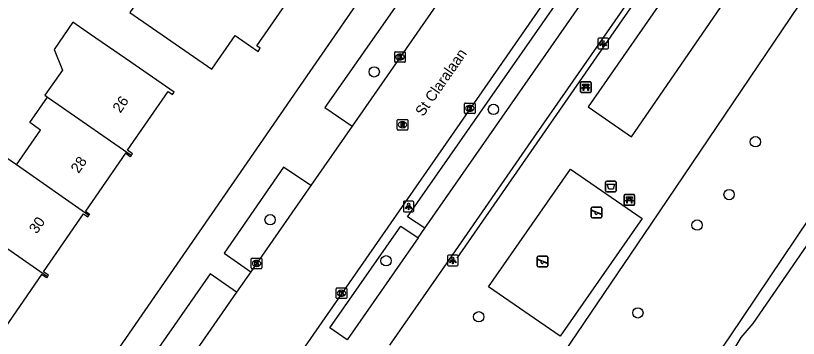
# Model space of a CAD drawing. Extents: x 160158 to 160921, y 381517 to 382041.
# Drawn here: x 160666.6 to 160740.7, y 381660.1 to 381690.7 of the extents above; entities that cross this region are included whole.
import ezdxf

# ---------------------------------------------------------------- set-up
doc = ezdxf.new("R2010")
doc.units = 0
for name, color, linetype in [('IMGEO_Afvalbak', 7, 'Continuous'), ('IMGEO_Bank', 7, 'Continuous'), ('IMGEO_Boom', 7, 'Continuous'), ('IMGEO_Fietspad_open', 7, 'Continuous'), ('IMGEO_Groenvoorziening', 7, 'Continuous'), ('IMGEO_Hek', 7, 'Continuous'), ('IMGEO_Kolk', 7, 'Continuous'), ('IMGEO_Lichtpunt', 7, 'Continuous'), ('IMGEO_Loofbos', 7, 'Continuous'), ('IMGEO_Openbare_ruimte_label', 7, 'Continuous'), ('IMGEO_Pand', 7, 'Continuous'), ('IMGEO_Pand_nummerreeks', 7, 'Continuous'), ('IMGEO_Rijbaan_lokaal_open', 7, 'Continuous'), ('IMGEO_Rioolput', 7, 'Continuous'), ('IMGEO_Speelvoorziening', 7, 'Continuous'), ('IMGEO_Voetpad_open', 7, 'Continuous'), ('IMGEO_Waterloop', 7, 'Continuous')]:
    doc.layers.add(name, color=color, linetype=linetype)

msp = doc.modelspace()

# ---------------------------------------------------------------- linework, layer by layer
at = {"layer": 'IMGEO_Afvalbak'}
for p, q in [((160722.423, 381674.074), (160722.423, 381674.874)), ((160722.423, 381674.874), (160722.423, 381674.074)), ((160722.523, 381674.974), (160723.313, 381674.974)), ((160723.313, 381674.974), (160722.523, 381674.974)), ((160723.413, 381674.874), (160723.413, 381674.074)), ((160723.413, 381674.074), (160723.413, 381674.874)), ((160723.313, 381673.974), (160722.523, 381673.974)), ((160722.523, 381673.974), (160723.313, 381673.974))]:
    msp.add_line(p, q, dxfattribs=at)
msp.add_lwpolyline([(160722.566, 381674.688), (160723.27, 381674.688), (160723.121, 381674.218), (160722.715, 381674.218), (160722.566, 381674.688)], dxfattribs=at)
for centre, start, end in [((160722.523, 381674.874), 90, 180), ((160722.523, 381674.874), 90, 180), ((160723.313, 381674.874), 0, 90), ((160723.313, 381674.874), 360, 90), ((160722.523, 381674.074), 180, 270), ((160722.523, 381674.074), 180, 270), ((160723.313, 381674.074), 270, 0), ((160723.313, 381674.074), 270, 0)]:
    msp.add_arc(centre, 0.1, start, end, dxfattribs=at)
at = {"layer": 'IMGEO_Bank'}
for p, q in [((160720.047, 381683.461), (160720.047, 381684.302)), ((160720.047, 381684.302), (160720.047, 381683.461)), ((160720.122, 381684.386), (160720.963, 381684.386)), ((160720.963, 381684.386), (160720.122, 381684.386)), ((160720.744, 381683.784), (160720.351, 381683.784)), ((160720.356, 381683.892), (160720.356, 381683.998)), ((160720.4, 381683.998), (160720.4, 381683.892)), ((160720.688, 381684.004), (160720.406, 381684.004)), ((160720.406, 381683.886), (160720.688, 381683.886)), ((160720.694, 381683.892), (160720.694, 381683.998)), ((160720.738, 381683.998), (160720.738, 381683.892)), ((160721.047, 381684.311), (160721.047, 381683.47)), ((160721.047, 381683.47), (160721.047, 381684.311)), ((160720.972, 381683.386), (160720.131, 381683.386)), ((160720.131, 381683.386), (160720.972, 381683.386)), ((160724.166, 381672.785), (160724.166, 381673.626)), ((160724.166, 381673.626), (160724.166, 381672.785)), ((160724.241, 381673.71), (160725.082, 381673.71)), ((160725.082, 381673.71), (160724.241, 381673.71)), ((160725.166, 381673.635), (160725.166, 381672.794)), ((160725.166, 381672.794), (160725.166, 381673.635)), ((160725.091, 381672.71), (160724.25, 381672.71)), ((160724.25, 381672.71), (160725.091, 381672.71)), ((160724.863, 381673.108), (160724.47, 381673.108)), ((160724.475, 381673.216), (160724.475, 381673.322)), ((160724.519, 381673.322), (160724.519, 381673.216)), ((160724.807, 381673.328), (160724.525, 381673.328)), ((160724.525, 381673.21), (160724.807, 381673.21)), ((160724.813, 381673.216), (160724.813, 381673.322)), ((160724.857, 381673.322), (160724.857, 381673.216))]:
    msp.add_line(p, q, dxfattribs=at)
for points in [[(160720.294, 381683.784), (160720.152, 381683.784), (160720.264, 381683.886), (160720.35, 381683.886)], [(160720.35, 381684.004), (160720.264, 381684.004), (160720.264, 381684.165), (160720.827, 381684.165), (160720.827, 381684.004), (160720.744, 381684.004)], [(160720.344, 381683.777), (160720.344, 381683.57), (160720.301, 381683.57), (160720.301, 381683.777)], [(160720.744, 381683.886), (160720.827, 381683.886), (160720.939, 381683.784), (160720.8, 381683.784)], [(160720.794, 381683.777), (160720.794, 381683.57), (160720.75, 381683.57), (160720.75, 381683.777)], [(160724.469, 381673.328), (160724.383, 381673.328), (160724.383, 381673.489), (160724.946, 381673.489), (160724.946, 381673.328), (160724.863, 381673.328)], [(160724.413, 381673.108), (160724.271, 381673.108), (160724.383, 381673.21), (160724.469, 381673.21)], [(160724.463, 381673.101), (160724.463, 381672.894), (160724.42, 381672.894), (160724.42, 381673.101)], [(160724.863, 381673.21), (160724.946, 381673.21), (160725.058, 381673.108), (160724.919, 381673.108)], [(160724.913, 381673.101), (160724.913, 381672.894), (160724.869, 381672.894), (160724.869, 381673.101)]]:
    msp.add_lwpolyline(points, dxfattribs=at)
for centre, radius, start, end in [((160720.125, 381684.308), 0.0779, 92.4484, 184.28452), ((160720.125, 381684.308), 0.0779, 92.4484, 184.28452), ((160720.294, 381683.777), 0.00671, 2.89567, 87.10433), ((160720.351, 381683.777), 0.00671, 92.89567, 177.10433), ((160720.349, 381683.997), 0.00671, 2.89567, 87.10433), ((160720.349, 381683.893), 0.00671, 272.89567, 357.10433), ((160720.406, 381683.997), 0.00671, 92.89567, 177.10433), ((160720.406, 381683.893), 0.00671, 182.89567, 267.10433), ((160720.688, 381683.997), 0.00671, 2.89567, 87.10433), ((160720.688, 381683.893), 0.00671, 272.89567, 357.10433), ((160720.745, 381683.997), 0.00671, 92.89567, 177.10433), ((160720.745, 381683.893), 0.00671, 182.89567, 267.10433), ((160720.743, 381683.777), 0.00671, 2.89567, 87.10433), ((160720.8, 381683.777), 0.00671, 92.89567, 177.10433), ((160720.969, 381684.308), 0.0779, 2.4484, 94.28452), ((160720.969, 381684.308), 0.0779, 2.4484, 94.28452), ((160720.125, 381683.464), 0.0779, 182.4484, 274.28452), ((160720.125, 381683.464), 0.0779, 182.4484, 274.28452), ((160720.969, 381683.464), 0.0779, 272.4484, 4.28452), ((160720.969, 381683.464), 0.0779, 272.4484, 4.28452), ((160724.244, 381673.632), 0.0779, 92.4484, 184.28452), ((160724.244, 381673.632), 0.0779, 92.4484, 184.28452), ((160725.088, 381673.632), 0.0779, 2.4484, 94.28452), ((160725.088, 381673.632), 0.0779, 2.4484, 94.28452), ((160724.244, 381672.788), 0.0779, 182.4484, 274.28452), ((160724.244, 381672.788), 0.0779, 182.4484, 274.28452), ((160724.413, 381673.101), 0.00671, 2.89567, 87.10433), ((160724.47, 381673.101), 0.00671, 92.89567, 177.10433), ((160724.468, 381673.321), 0.00671, 2.89567, 87.10433), ((160724.468, 381673.217), 0.00671, 272.89567, 357.10433), ((160724.525, 381673.321), 0.00671, 92.89567, 177.10433), ((160724.525, 381673.217), 0.00671, 182.89567, 267.10433), ((160724.807, 381673.321), 0.00671, 2.89567, 87.10433), ((160724.807, 381673.217), 0.00671, 272.89567, 357.10433), ((160724.864, 381673.321), 0.00671, 92.89567, 177.10433), ((160724.864, 381673.217), 0.00671, 182.89567, 267.10433), ((160724.862, 381673.101), 0.00671, 2.89567, 87.10433), ((160724.919, 381673.101), 0.00671, 92.89567, 177.10433), ((160725.088, 381672.788), 0.0779, 272.4484, 4.28452), ((160725.088, 381672.788), 0.0779, 272.4484, 4.28452)]:
    msp.add_arc(centre, radius, start, end, dxfattribs=at)
at = {"layer": 'IMGEO_Boom'}
for centre in [(160700.516, 381685.34), (160711.805, 381681.78), (160736.598, 381678.723), (160734.111, 381673.707), (160690.669, 381671.331), (160731.077, 381670.823), (160701.64, 381667.44), (160710.41, 381662.131), (160725.469, 381662.504)]:
    msp.add_circle(centre, 0.489, dxfattribs=at)
at = {"layer": 'IMGEO_Fietspad_open'}
for points in [[(160750.884, 381729.902), (160715.353, 381678.728), (160707.599, 381667.561), (160701.965, 381659.446)], [(160705.315, 381670.539), (160726.771, 381701.377)], [(160704.668, 381669.608), (160705.315, 381670.539)], [(160704.668, 381669.608), (160697.946, 381659.948)]]:
    msp.add_lwpolyline(points, dxfattribs=at)
at = {"layer": 'IMGEO_Groenvoorziening'}
for points in [[(160720.77, 381682.025), (160724.882, 381679.185), (160733.282, 381691.433), (160729.203, 381694.182), (160720.77, 381682.025)], [(160725.872, 381671.46), (160718.106, 381660.295), (160711.346, 381664.96), (160719.106, 381676.122), (160725.872, 381671.46)]]:
    msp.add_lwpolyline(points, dxfattribs=at)
at = {"layer": 'IMGEO_Hek'}
msp.add_lwpolyline([(160735.576, 381706.994), (160708.335, 381667.698)], dxfattribs=at)
at = {"layer": 'IMGEO_Kolk'}
for p, q in [((160702.46, 381686.319), (160702.46, 381687.171)), ((160702.535, 381687.245), (160703.387, 381687.245)), ((160702.948, 381687.025), (160702.973, 381687.025)), ((160703.461, 381687.171), (160703.461, 381686.319)), ((160703.387, 381686.245), (160702.535, 381686.245)), ((160702.971, 381686.465), (160702.946, 381686.465)), ((160709.072, 381681.461), (160709.072, 381682.313)), ((160709.147, 381682.387), (160709.999, 381682.387)), ((160710.073, 381682.313), (160710.073, 381681.461)), ((160709.583, 381681.607), (160709.558, 381681.607)), ((160709.56, 381682.167), (160709.585, 381682.167)), ((160709.999, 381681.387), (160709.147, 381681.387)), ((160688.883, 381666.759), (160688.883, 381667.611)), ((160688.958, 381667.685), (160689.81, 381667.685)), ((160689.371, 381667.465), (160689.396, 381667.465)), ((160689.884, 381667.611), (160689.884, 381666.759)), ((160689.394, 381666.905), (160689.369, 381666.905)), ((160689.81, 381666.685), (160688.958, 381666.685)), ((160696.918, 381663.94), (160696.918, 381664.792)), ((160696.993, 381664.866), (160697.845, 381664.866)), ((160697.406, 381664.646), (160697.431, 381664.646)), ((160697.919, 381664.792), (160697.919, 381663.94)), ((160697.845, 381663.866), (160696.993, 381663.866)), ((160697.429, 381664.086), (160697.404, 381664.086))]:
    msp.add_line(p, q, dxfattribs=at)
for points in [[(160702.46, 381686.319), (160702.46, 381687.171)], [(160702.535, 381687.245), (160703.387, 381687.245)], [(160702.781, 381686.945), (160702.904, 381686.945), (160702.904, 381686.794), (160703.034, 381686.945), (160703.198, 381686.945), (160703.052, 381686.794), (160703.205, 381686.545), (160703.053, 381686.545), (160702.968, 381686.709), (160702.904, 381686.642), (160702.904, 381686.545), (160702.781, 381686.545), (160702.781, 381686.945)], [(160703.461, 381687.171), (160703.461, 381686.319)], [(160703.387, 381686.245), (160702.535, 381686.245)], [(160709.072, 381681.461), (160709.072, 381682.313)], [(160709.147, 381682.387), (160709.999, 381682.387)], [(160710.073, 381682.313), (160710.073, 381681.461)], [(160709.393, 381682.087), (160709.516, 381682.087), (160709.516, 381681.936), (160709.646, 381682.087), (160709.81, 381682.087), (160709.664, 381681.936), (160709.817, 381681.687), (160709.665, 381681.687), (160709.58, 381681.851), (160709.516, 381681.784), (160709.516, 381681.687), (160709.393, 381681.687), (160709.393, 381682.087)], [(160709.999, 381681.387), (160709.147, 381681.387)], [(160688.883, 381666.759), (160688.883, 381667.611)], [(160688.958, 381667.685), (160689.81, 381667.685)], [(160689.884, 381667.611), (160689.884, 381666.759)], [(160689.204, 381667.385), (160689.327, 381667.385), (160689.327, 381667.234), (160689.457, 381667.385), (160689.621, 381667.385), (160689.475, 381667.234), (160689.628, 381666.985), (160689.476, 381666.985), (160689.391, 381667.149), (160689.327, 381667.082), (160689.327, 381666.985), (160689.204, 381666.985), (160689.204, 381667.385)], [(160689.81, 381666.685), (160688.958, 381666.685)], [(160696.918, 381663.94), (160696.918, 381664.792)], [(160696.993, 381664.866), (160697.845, 381664.866)], [(160697.239, 381664.566), (160697.362, 381664.566), (160697.362, 381664.415), (160697.492, 381664.566), (160697.656, 381664.566), (160697.51, 381664.415), (160697.663, 381664.166), (160697.511, 381664.166), (160697.426, 381664.33), (160697.362, 381664.263), (160697.362, 381664.166), (160697.239, 381664.166), (160697.239, 381664.566)], [(160697.919, 381664.792), (160697.919, 381663.94)], [(160697.845, 381663.866), (160696.993, 381663.866)]]:
    msp.add_lwpolyline(points, dxfattribs=at)
for centre, start, end in [((160702.537, 381687.169), 91.55205, 178.44795), ((160702.537, 381687.169), 91.55205, 178.44795), ((160703.385, 381687.169), 1.55205, 88.44795), ((160703.385, 381687.169), 1.55205, 88.44795), ((160702.537, 381686.321), 181.55205, 268.44795), ((160702.537, 381686.321), 181.55205, 268.44795), ((160703.385, 381686.321), 271.55205, 358.44795), ((160703.385, 381686.321), 271.55205, 358.44795), ((160709.149, 381682.311), 91.55205, 178.44795), ((160709.149, 381682.311), 91.55205, 178.44795), ((160709.997, 381682.311), 1.55205, 88.44795), ((160709.997, 381682.311), 1.55205, 88.44795), ((160709.149, 381681.463), 181.55205, 268.44795), ((160709.149, 381681.463), 181.55205, 268.44795), ((160709.997, 381681.463), 271.55205, 358.44795), ((160709.997, 381681.463), 271.55205, 358.44795), ((160688.96, 381667.609), 91.55205, 178.44795), ((160688.96, 381667.609), 91.55205, 178.44795), ((160689.808, 381667.609), 1.55205, 88.44795), ((160689.808, 381667.609), 1.55205, 88.44795), ((160688.96, 381666.761), 181.55205, 268.44795), ((160688.96, 381666.761), 181.55205, 268.44795), ((160689.808, 381666.761), 271.55205, 358.44795), ((160689.808, 381666.761), 271.55205, 358.44795), ((160696.995, 381664.79), 91.55205, 178.44795), ((160696.995, 381664.79), 91.55205, 178.44795), ((160697.843, 381664.79), 1.55205, 88.44795), ((160697.843, 381664.79), 1.55205, 88.44795), ((160696.995, 381663.942), 181.55205, 268.44795), ((160696.995, 381663.942), 181.55205, 268.44795), ((160697.843, 381663.942), 271.55205, 358.44795), ((160697.843, 381663.942), 271.55205, 358.44795)]:
    msp.add_arc(centre, 0.0765, start, end, dxfattribs=at)
for centre, major_axis, ratio, start_param, end_param in [((160702.947, 381686.745), (-0.387, 0.002), 0.722429, 4.712389, 7.853982), ((160702.972, 381686.745), (-0.39, 0.002), 0.717154, 1.570796, 4.712389), ((160709.559, 381681.887), (-0.387, 0.002), 0.722429, 4.712389, 7.853982), ((160709.584, 381681.887), (-0.39, 0.002), 0.717154, 1.570796, 4.712389), ((160689.37, 381667.185), (-0.387, 0.002), 0.722429, 4.712389, 7.853982), ((160689.395, 381667.185), (-0.39, 0.002), 0.717154, 1.570796, 4.712389), ((160697.405, 381664.366), (-0.387, 0.002), 0.722429, 4.712389, 7.853982), ((160697.43, 381664.366), (-0.39, 0.002), 0.717154, 1.570796, 4.712389)]:
    msp.add_ellipse(centre, major_axis=major_axis, ratio=ratio, start_param=start_param, end_param=end_param, dxfattribs=at)
at = {"layer": 'IMGEO_Lichtpunt'}
for p, q in [((160721.689, 381688.424), (160721.689, 381687.617)), ((160721.689, 381688.424), (160721.689, 381687.617)), ((160722.591, 381688.519), (160721.783, 381688.519)), ((160722.591, 381688.519), (160721.783, 381688.519)), ((160722.685, 381687.617), (160722.685, 381688.424)), ((160722.685, 381687.617), (160722.685, 381688.424)), ((160721.783, 381687.523), (160722.591, 381687.523)), ((160721.783, 381687.523), (160722.591, 381687.523)), ((160703.277, 381672.986), (160703.277, 381672.179)), ((160703.277, 381672.986), (160703.277, 381672.179)), ((160704.179, 381673.081), (160703.371, 381673.081)), ((160704.179, 381673.081), (160703.371, 381673.081)), ((160704.273, 381672.179), (160704.273, 381672.986)), ((160704.273, 381672.179), (160704.273, 381672.986)), ((160703.371, 381672.085), (160704.179, 381672.085)), ((160703.371, 381672.085), (160704.179, 381672.085)), ((160707.459, 381667.87), (160707.459, 381667.063)), ((160707.459, 381667.87), (160707.459, 381667.063)), ((160708.361, 381667.965), (160707.553, 381667.965)), ((160708.361, 381667.965), (160707.553, 381667.965)), ((160708.455, 381667.063), (160708.455, 381667.87)), ((160708.455, 381667.063), (160708.455, 381667.87)), ((160707.553, 381666.969), (160708.361, 381666.969)), ((160707.553, 381666.969), (160708.361, 381666.969))]:
    msp.add_line(p, q, dxfattribs=at)
for points in [[(160722.063, 381688.088), (160722.102, 381688.06), (160721.914, 381687.798), (160721.876, 381687.825), (160722.063, 381688.088)], [(160722.165, 381688.04), (160722.212, 381688.04), (160722.212, 381687.718), (160722.165, 381687.718), (160722.165, 381688.04)], [(160722.275, 381688.06), (160722.313, 381688.087), (160722.5, 381687.825), (160722.461, 381687.797), (160722.275, 381688.06)], [(160703.651, 381672.65), (160703.69, 381672.622), (160703.502, 381672.36), (160703.464, 381672.387), (160703.651, 381672.65)], [(160703.863, 381672.622), (160703.901, 381672.649), (160704.088, 381672.387), (160704.049, 381672.359), (160703.863, 381672.622)], [(160703.753, 381672.602), (160703.8, 381672.602), (160703.8, 381672.28), (160703.753, 381672.28), (160703.753, 381672.602)], [(160707.833, 381667.534), (160707.872, 381667.506), (160707.684, 381667.244), (160707.646, 381667.271), (160707.833, 381667.534)], [(160707.935, 381667.486), (160707.982, 381667.486), (160707.982, 381667.164), (160707.935, 381667.164), (160707.935, 381667.486)], [(160708.045, 381667.506), (160708.083, 381667.533), (160708.27, 381667.271), (160708.231, 381667.243), (160708.045, 381667.506)]]:
    msp.add_lwpolyline(points, dxfattribs=at)
for centre in [(160722.188, 381688.222), (160703.776, 381672.784), (160707.958, 381667.668)]:
    msp.add_circle(centre, 0.0994, dxfattribs=at)
for centre, start, end in [((160721.783, 381688.424), 90, 180), ((160721.783, 381688.424), 90, 180), ((160722.591, 381688.424), 0, 90), ((160722.591, 381688.424), 0, 90), ((160721.783, 381687.617), 180, 270), ((160721.783, 381687.617), 180, 270), ((160722.591, 381687.617), 270, 0), ((160722.591, 381687.617), 270, 360), ((160703.371, 381672.986), 90, 180), ((160703.371, 381672.986), 90, 180), ((160704.179, 381672.986), 0, 90), ((160704.179, 381672.986), 0, 90), ((160703.371, 381672.179), 180, 270), ((160703.371, 381672.179), 180, 270), ((160704.179, 381672.179), 270, 0), ((160704.179, 381672.179), 270, 360), ((160707.553, 381667.87), 90, 180), ((160707.553, 381667.87), 90, 180), ((160708.361, 381667.87), 0, 90), ((160708.361, 381667.87), 0, 90), ((160707.553, 381667.063), 180, 270), ((160707.553, 381667.063), 180, 270), ((160708.361, 381667.063), 270, 0), ((160708.361, 381667.063), 270, 360)]:
    msp.add_arc(centre, 0.0946, start, end, dxfattribs=at)
at = {"layer": 'IMGEO_Loofbos'}
for points in [[(160761.696, 381722.771), (160726.687, 381670.894), (160719.079, 381659.62), (160713.536, 381651.406)], [(160746.885, 381633.648), (160729.911, 381650.761), (160729.471, 381651.25), (160729.203, 381651.851), (160729.348, 381652.926), (160729.734, 381653.94), (160731.127, 381656.195), (160732.022, 381657.124), (160734.184, 381660.226), (160771.903, 381716.443)]]:
    msp.add_lwpolyline(points, dxfattribs=at)
at = {"layer": 'IMGEO_Pand'}
for points in [[(160686.905, 381697.836), (160683.698, 381700.057), (160677.4, 381690.964), (160685.162, 381685.587), (160687.342, 381688.795), (160689.535, 381687.277), (160689.737, 381687.569), (160689.393, 381687.807), (160693.136, 381693.215), (160693.474, 381692.981), (160693.59, 381693.149)], [(160677.526, 381677.443), (160677.625, 381677.587), (160677.16, 381677.908), (160681.011, 381683.484), (160681.434, 381683.192), (160681.584, 381683.409), (160677.469, 381686.25), (160673.657, 381688.883), (160671.994, 381690.031), (160670.215, 381687.455), (160670.999, 381685.503), (160669.352, 381683.117), (160669.585, 381682.956)], [(160666.67, 381676.54), (160668.941, 381679.828), (160667.914, 381680.537), (160669.585, 381682.956)], [(160669.585, 381682.956), (160670.613, 381682.246), (160677.526, 381677.443)], [(160666.67, 381676.54), (160665.663, 381677.235), (160663.965, 381674.776), (160664.973, 381674.081), (160662.677, 381670.756)], [(160677.526, 381677.443), (160677.428, 381677.301), (160676.961, 381677.624), (160673.175, 381672.141), (160673.584, 381671.858), (160673.499, 381671.735)], [(160673.499, 381671.735), (160666.67, 381676.54)], [(160669.585, 381665.947), (160669.674, 381666.076), (160669.217, 381666.391), (160673.012, 381671.887), (160673.413, 381671.61), (160673.499, 381671.735)], [(160662.677, 381670.756), (160669.585, 381665.947)], [(160669.585, 381665.947), (160669.496, 381665.819), (160669.033, 381666.139), (160665.261, 381660.677), (160665.734, 381660.35), (160665.647, 381660.223)]]:
    msp.add_lwpolyline(points, dxfattribs=at)
at = {"layer": 'IMGEO_Rijbaan_lokaal_open'}
for points in [[(160673.052, 381629.169), (160742.168, 381728.75), (160744.459, 381732.031), (160749.187, 381738.841), (160756.939, 381750), (160765.763, 381763.144), (160772.954, 381773.374), (160774.36, 381775.443), (160780.995, 381784.58)], [(160708.147, 381694.213), (160698.421, 381680.201)], [(160698.421, 381680.201), (160694.523, 381674.586)], [(160694.523, 381674.586), (160688.846, 381666.406)], [(160688.846, 381666.406), (160687.489, 381664.451)], [(160687.489, 381664.451), (160679.971, 381653.62)]]:
    msp.add_lwpolyline(points, dxfattribs=at)
at = {"layer": 'IMGEO_Rioolput'}
for p, q in [((160702.769, 381680.826), (160703.621, 381680.826)), ((160702.694, 381679.9), (160702.694, 381680.752)), ((160703.205, 381680.046), (160703.18, 381680.046)), ((160703.182, 381680.606), (160703.207, 381680.606)), ((160703.695, 381680.752), (160703.695, 381679.9)), ((160703.621, 381679.826), (160702.769, 381679.826))]:
    msp.add_line(p, q, dxfattribs=at)
for points in [[(160702.769, 381680.826), (160703.621, 381680.826)], [(160702.694, 381679.9), (160702.694, 381680.752)], [(160703.283, 381680.524), (160703.031, 381680.526), (160703.031, 381680.126)], [(160703.031, 381680.126), (160703.155, 381680.126), (160703.155, 381680.288), (160703.166, 381680.288)], [(160703.209, 381680.445), (160703.155, 381680.445), (160703.155, 381680.364)], [(160703.155, 381680.364), (160703.207, 381680.364)], [(160703.213, 381680.259), (160703.284, 381680.126), (160703.424, 381680.126), (160703.359, 381680.252)], [(160703.695, 381680.752), (160703.695, 381679.9)], [(160703.621, 381679.826), (160702.769, 381679.826)]]:
    msp.add_lwpolyline(points, dxfattribs=at)
for centre, radius, start, end in [((160702.771, 381680.75), 0.0765, 91.55205, 178.44795), ((160702.771, 381680.75), 0.0765, 91.55205, 178.44795), ((160703.619, 381680.75), 0.0765, 1.55205, 88.44795), ((160703.619, 381680.75), 0.0765, 1.55205, 88.44795), ((160703.165, 381680.235), 0.0533, 26.02933, 88.69889), ((160703.191, 381680.553), 0.19, 274.7715, 282.96867), ((160703.215, 381680.349), 0.0964, 77.00612, 93.18647), ((160703.229, 381680.406), 0.0378, 276.66336, 79.67722), ((160703.282, 381680.414), 0.109, 350.36119, 89.41601), ((160703.28, 381680.414), 0.112, 277.58423, 350.98172), ((160703.264, 381680.199), 0.108, 29.51342, 73.79051), ((160702.771, 381679.902), 0.0765, 181.55205, 268.44795), ((160702.771, 381679.902), 0.0765, 181.55205, 268.44795), ((160703.619, 381679.902), 0.0765, 271.55205, 358.44795), ((160703.619, 381679.902), 0.0765, 271.55205, 358.44795)]:
    msp.add_arc(centre, radius, start, end, dxfattribs=at)
for centre, major_axis, ratio, start_param, end_param in [((160703.181, 381680.326), (-0.387, 0.002), 0.722429, 4.712389, 7.853982), ((160703.206, 381680.326), (-0.39, 0.002), 0.717154, 1.570796, 4.712389)]:
    msp.add_ellipse(centre, major_axis=major_axis, ratio=ratio, start_param=start_param, end_param=end_param, dxfattribs=at)
at = {"layer": 'IMGEO_Speelvoorziening'}
for p, q in [((160721.065, 381671.615), (160721.065, 381672.415)), ((160721.065, 381672.415), (160721.065, 381671.615)), ((160721.448, 381672.043), (160721.109, 381672.18)), ((160721.134, 381672.24), (160722.01, 381671.887)), ((160721.165, 381672.515), (160721.955, 381672.515)), ((160721.955, 381672.515), (160721.165, 381672.515)), ((160721.986, 381671.827), (160721.646, 381671.964)), ((160722.055, 381672.415), (160722.055, 381671.615)), ((160722.055, 381671.615), (160722.055, 381672.415)), ((160721.955, 381671.515), (160721.165, 381671.515)), ((160721.165, 381671.515), (160721.955, 381671.515)), ((160715.953, 381666.967), (160715.953, 381667.767)), ((160715.953, 381667.767), (160715.953, 381666.967)), ((160716.336, 381667.395), (160715.997, 381667.532)), ((160716.022, 381667.592), (160716.898, 381667.239)), ((160716.053, 381667.867), (160716.843, 381667.867)), ((160716.843, 381667.867), (160716.053, 381667.867)), ((160716.943, 381667.767), (160716.943, 381666.967)), ((160716.943, 381666.967), (160716.943, 381667.767)), ((160716.843, 381666.867), (160716.053, 381666.867)), ((160716.053, 381666.867), (160716.843, 381666.867)), ((160716.874, 381667.179), (160716.534, 381667.316))]:
    msp.add_line(p, q, dxfattribs=at)
for centre, radius, start, end in [((160721.165, 381672.415), 0.1, 90, 180), ((160721.165, 381672.415), 0.1, 90, 180), ((160721.122, 381672.21), 0.0327, 68.07798, 248.07798), ((160721.527, 381671.953), 0.12, 130.99278, 5.16318), ((160721.955, 381672.415), 0.1, 0, 90), ((160721.955, 381672.415), 0.1, 360, 90), ((160721.165, 381671.615), 0.1, 180, 270), ((160721.165, 381671.615), 0.1, 180, 270), ((160721.955, 381671.615), 0.1, 270, 0), ((160721.955, 381671.615), 0.1, 270, 0), ((160721.998, 381671.857), 0.0327, 248.07798, 68.07798), ((160716.053, 381667.767), 0.1, 90, 180), ((160716.053, 381667.767), 0.1, 90, 180), ((160716.01, 381667.562), 0.0327, 68.07798, 248.07798), ((160716.843, 381667.767), 0.1, 0, 90), ((160716.843, 381667.767), 0.1, 360, 90), ((160716.053, 381666.967), 0.1, 180, 270), ((160716.053, 381666.967), 0.1, 180, 270), ((160716.415, 381667.305), 0.12, 130.99278, 5.16318), ((160716.843, 381666.967), 0.1, 270, 0), ((160716.843, 381666.967), 0.1, 270, 0), ((160716.886, 381667.209), 0.0327, 248.07798, 68.07798)]:
    msp.add_arc(centre, radius, start, end, dxfattribs=at)
at = {"layer": 'IMGEO_Voetpad_open'}
for points in [[(160661.788, 381640.317), (160662.531, 381640.256), (160663.603, 381640.788), (160664.019, 381641.292), (160689.395, 381678.051), (160693.253, 381683.64), (160710.372, 381708.438)], [(160705.315, 381670.539), (160703.659, 381671.601), (160725.16, 381702.466), (160726.771, 381701.377)], [(160708.147, 381694.213), (160705.636, 381695.946), (160695.854, 381681.967), (160698.421, 381680.201)], [(160694.523, 381674.586), (160691.929, 381676.324), (160686.312, 381668.154), (160688.846, 381666.406)], [(160697.946, 381659.948), (160696.326, 381661.075), (160703.044, 381670.718), (160704.668, 381669.608)], [(160687.489, 381664.451), (160684.982, 381666.207), (160677.443, 381655.379), (160679.971, 381653.62)]]:
    msp.add_lwpolyline(points, dxfattribs=at)
at = {"layer": 'IMGEO_Waterloop'}
msp.add_lwpolyline([(160773.417, 381715.353), (160736.362, 381661.508), (160735.221, 381660.18), (160733.599, 381657.473), (160730.786, 381653.368), (160730.545, 381652.698), (160730.789, 381652.03), (160734.978, 381647.464), (160741.419, 381641.497), (160754.511, 381628.641), (160765.982, 381624.678), (160768.45, 381623.595), (160771.127, 381621.922), (160782.581, 381610.619), (160782.838, 381610.409), (160784.258, 381609.248), (160784.487, 381609.061), (160789.482, 381604.193)], dxfattribs=at)

# ---------------------------------------------------------------- texts
at = {"layer": 'IMGEO_Openbare_ruimte_label'}
msp.add_text('St Claralaan', height=1, rotation=55.26137, dxfattribs=at).set_placement((160705.145, 381681.045))
at = {"layer": 'IMGEO_Pand_nummerreeks'}
for s, rotation, p in [('26', 55.35918, (160676.491, 381681.375)), ('28', 55.35632, (160672.536, 381675.654)), ('30', 55.35632, (160668.581, 381669.93))]:
    msp.add_text(s, height=1, rotation=rotation, dxfattribs=at).set_placement(p)

doc.saveas('drawing.dxf')
